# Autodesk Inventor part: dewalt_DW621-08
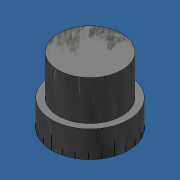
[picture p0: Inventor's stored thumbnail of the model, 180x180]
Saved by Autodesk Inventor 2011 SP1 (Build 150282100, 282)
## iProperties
Created: 2011-02
Part Number: dewalt_DW621-08
Material: Kst - PA6.6 Gf30(schwarz)
Catalog Web Link: www.mittelmeyer.de
Document SubType Name: Modellieren
Designer: TMT
Manufacturer: Standard
Standards Organization: Custom
Density: 1.14 g/cm^3
Author: TMT
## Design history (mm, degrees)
sketch "Skizze2"
  geometry: C1 r 14.5 at (0, 0); 1 further point
  constraints: 1 centre point, 1 coincident
  dimensions: "d5" = 29 diameter of C1 (= durchmesser_01)
extrude "Extrusion2" new body sketch "Skizze2" distance "d6" = 10 (= hoehe_01); taper "d7" = 0 deg
sketch "Skizze3"
  geometry: C1 r 14.5 at (0, 0) reference; C2 r 12 at (0, 0)
  constraints: 1 centre point, 1 coincident
  dimensions: "d8" = 24 diameter of C2
extrude "Extrusion3" join sketch "Skizze3" distance "d9" = 15; taper "d10" = 0 deg
sketch "Skizze4"
  geometry: L1 (20.3, 0)-(-20.3, 0) reference; L2 (0, -20.3)-(0, 20.3) reference; L3 (0.05, -14.5)-(0.05, -14.55); L4 (0.05, -14.55)-(-0.05, -14.55); L5 (-0.05, -14.55)-(-0.05, -14.5); A1 r 14.5 centre (0, 0) between (0.05, -14.5) and (-0.05, -14.5) reference
  constraints: 6 end point, 2 point on circle, 1 parallel, 1 perpendicular, 1 other
  dimensions: "d23" = 0.1 distance of L3.end L4.end; "d24" = 0.05 distance of L4.end L5.end
extrude "Extrusion4" join sketch "Skizze4" distance "d13" = 2; taper "d14" = 0 deg
sketch "Skizze6"
  geometry: L1 (0.05, -14.5)-(0.05, -14.55) reference; L2 (-0.05, -14.55)-(-0.05, -14.5) reference; L3 (0.05, -14.55)-(-0.05, -14.55) reference; A1 r 14.5 centre (0, 0) between (-0.05, -14.5) and (0.05, -14.5) reference
extrude "Extrusion6" join sketch "Skizze6" distance "d25" = 3; taper "d26" = 0 deg
pattern_circular "Runde Anordnung3" dims angle "d28" = 360 deg
node "Volumenkörper1"
node "Volumenkörpern"
node "Oberflächenkörpern"
pattern_circular "Runde Anordnung1" dims angle "d16" = 360 deg
other parameters: "durchmesser_01" = 29 [user parameter; used in 1 equation term], "hoehe_01" = 10 [user parameter; used in 1 equation term]
